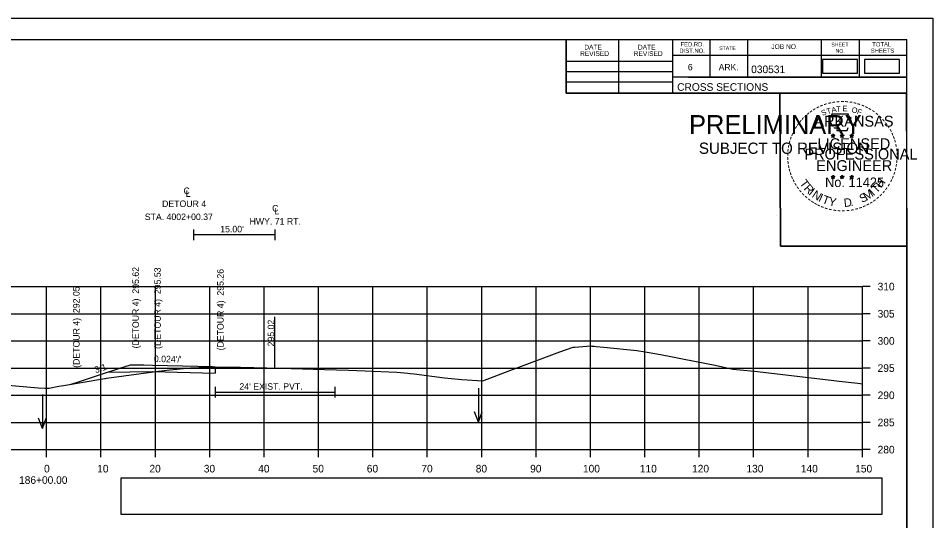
# Model space of a CAD drawing. Extents: x 285 to 4233, y -659 to 3710.
# Drawn here: x 1218.5 to 1386.6, y 2639.9 to 2732.3 of the extents above; entities that cross this region are included whole.
import ezdxf

# ---------------------------------------------------------------- set-up
doc = ezdxf.new("R2010")
doc.units = 0
for name, color, linetype in [('R_Alt Surface', 7, 'Continuous'), ('R_Axis', 7, 'Continuous'), ('R_Axis Annot', 7, 'Continuous'), ('R_Border', 7, 'Continuous'), ('R_Border PE', 7, 'Continuous'), ('R_Border Prem', 7, 'Continuous'), ('R_Detour', 7, 'Continuous'), ('R_Detour Annot', 7, 'Continuous'), ('R_Exist Surface', 7, 'Continuous'), ('R_Grid', 7, 'Continuous'), ('R_No Plot', 7, 'Continuous'), ('R_Water', 7, 'Continuous'), ('R_Water Annot', 7, 'Continuous'), ('R_Xsect Elev', 7, 'Continuous')]:
    doc.layers.add(name, color=color, linetype=linetype)

msp = doc.modelspace()

# ---------------------------------------------------------------- linework, layer by layer
at = {"layer": 'R_Alt Surface'}
for points in [[(1250.68, 2693.45), (1250.68, 2691.45)], [(1265.68, 2693.45), (1265.68, 2691.45)], [(1265.68, 2692.45), (1250.68, 2692.45)], [(1254.68, 2664.51), (1254.68, 2662.51)], [(1254.68, 2663.51), (1276.68, 2663.51)], [(1276.68, 2664.51), (1276.68, 2662.51)]]:
    msp.add_lwpolyline(points, dxfattribs=at)
at = {"layer": 'R_Axis'}
for p, q in [((1373.68, 2652.93), (1373.68, 2682.93)), ((1375.08, 2682.93), (1373.68, 2682.93)), ((1375.08, 2677.93), (1373.68, 2677.93)), ((1375.08, 2672.93), (1373.68, 2672.93)), ((1375.08, 2667.93), (1373.68, 2667.93)), ((1375.08, 2662.93), (1373.68, 2662.93)), ((1375.08, 2657.93), (1373.68, 2657.93)), ((1073.68, 2652.93), (1373.68, 2652.93)), ((1223.68, 2651.53), (1223.68, 2652.93)), ((1233.68, 2651.53), (1233.68, 2652.93)), ((1243.68, 2651.53), (1243.68, 2652.93)), ((1253.68, 2651.53), (1253.68, 2652.93)), ((1263.68, 2651.53), (1263.68, 2652.93)), ((1273.68, 2651.53), (1273.68, 2652.93)), ((1283.68, 2651.53), (1283.68, 2652.93)), ((1293.68, 2651.53), (1293.68, 2652.93)), ((1303.68, 2651.53), (1303.68, 2652.93)), ((1313.68, 2651.53), (1313.68, 2652.93)), ((1323.68, 2651.53), (1323.68, 2652.93)), ((1333.68, 2651.53), (1333.68, 2652.93)), ((1343.68, 2651.53), (1343.68, 2652.93)), ((1353.68, 2651.53), (1353.68, 2652.93)), ((1363.68, 2651.53), (1363.68, 2652.93)), ((1373.68, 2651.53), (1373.68, 2652.93)), ((1375.08, 2652.93), (1373.68, 2652.93))]:
    msp.add_line(p, q, dxfattribs=at)
at = {"layer": 'R_Axis Annot'}
for points in [[(1366.36, 2722.17), (1372.81, 2722.17), (1372.81, 2724.73), (1366.36, 2724.73)], [(1374.05, 2722.17), (1380.51, 2722.17), (1380.51, 2724.73), (1374.05, 2724.73)], [(1237.31, 2641.05), (1377.31, 2641.05), (1377.31, 2647.7), (1237.31, 2647.7)]]:
    msp.add_lwpolyline(points, close=True, dxfattribs=at)
at = {"layer": 'R_Border'}
for p, q in [((1065.68, 2728.39), (1381.86, 2728.39)), ((1319.22, 2718.51), (1319.22, 2728.39)), ((1328.9, 2718.51), (1328.9, 2728.39)), ((1338.76, 2728.39), (1338.76, 2718.51)), ((1345.6, 2728.39), (1345.6, 2721.45)), ((1352.54, 2728.39), (1352.54, 2721.45)), ((1366.12, 2728.39), (1366.12, 2721.45)), ((1373.06, 2728.39), (1373.06, 2721.45)), ((1381.86, 2522.93), (1381.86, 2728.39)), ((1381.86, 2725.45), (1338.76, 2725.45)), ((1381.86, 2725.47), (1381.86, 2725.47)), ((1319.22, 2724.37), (1338.76, 2724.37)), ((1319.22, 2722.51), (1338.76, 2722.51)), ((1319.22, 2720.57), (1338.76, 2720.57)), ((1381.86, 2721.45), (1338.76, 2721.45)), ((1341.72, 2721.45), (1381.86, 2721.45)), ((1381.86, 2718.51), (1319.22, 2718.51))]:
    msp.add_line(p, q, dxfattribs=at)
at = {"layer": 'R_Border PE'}
for p, q in [((1367.94, 2710.76), (1368.29, 2710.65)), ((1367.94, 2710.76), (1368.19, 2710.72)), ((1367.94, 2710.76), (1368.18, 2710.64)), ((1368.07, 2710.36), (1368.29, 2710.65)), ((1368.07, 2710.36), (1368.2, 2710.6)), ((1368.07, 2710.36), (1368.29, 2710.57)), ((1368.29, 2711.02), (1368.25, 2710.77)), ((1368.29, 2710.65), (1368.29, 2711.02)), ((1368.29, 2711.02), (1368.34, 2710.77)), ((1368.64, 2710.76), (1368.29, 2710.65)), ((1368.5, 2710.36), (1368.29, 2710.65)), ((1368.5, 2710.36), (1368.29, 2710.57)), ((1368.64, 2710.76), (1368.35, 2710.72)), ((1368.5, 2710.36), (1368.37, 2710.65)), ((1368.64, 2710.76), (1368.43, 2710.66)), ((1369.61, 2710.76), (1369.96, 2710.65)), ((1369.61, 2710.76), (1369.86, 2710.72)), ((1369.61, 2710.76), (1369.85, 2710.64)), ((1369.74, 2710.36), (1369.96, 2710.65)), ((1369.74, 2710.36), (1369.87, 2710.6)), ((1369.74, 2710.36), (1369.96, 2710.57)), ((1369.96, 2711.02), (1369.92, 2710.77)), ((1369.96, 2710.65), (1369.96, 2711.02)), ((1369.96, 2711.02), (1370.01, 2710.77)), ((1370.31, 2710.76), (1369.96, 2710.65)), ((1370.17, 2710.36), (1369.96, 2710.65)), ((1370.17, 2710.36), (1369.96, 2710.57)), ((1370.31, 2710.76), (1370.02, 2710.72)), ((1370.17, 2710.36), (1370.04, 2710.65)), ((1370.31, 2710.76), (1370.1, 2710.66)), ((1371.38, 2710.75), (1371.72, 2710.64)), ((1371.38, 2710.75), (1371.63, 2710.71)), ((1371.38, 2710.75), (1371.61, 2710.63)), ((1371.51, 2710.34), (1371.72, 2710.64)), ((1371.51, 2710.34), (1371.63, 2710.59)), ((1371.51, 2710.34), (1371.72, 2710.56)), ((1371.72, 2711.01), (1371.68, 2710.75)), ((1371.72, 2710.64), (1371.72, 2711.01)), ((1371.72, 2711.01), (1371.77, 2710.76)), ((1372.07, 2710.75), (1371.72, 2710.64)), ((1371.94, 2710.34), (1371.72, 2710.64)), ((1371.94, 2710.34), (1371.72, 2710.56)), ((1372.07, 2710.75), (1371.79, 2710.7)), ((1371.94, 2710.34), (1371.8, 2710.64)), ((1372.07, 2710.75), (1371.87, 2710.65)), ((1367.94, 2703.19), (1368.29, 2703.08)), ((1367.94, 2703.19), (1368.19, 2703.15)), ((1367.94, 2703.19), (1368.17, 2703.07)), ((1368.07, 2702.78), (1368.29, 2703.08)), ((1368.07, 2702.78), (1368.2, 2703.03)), ((1368.07, 2702.78), (1368.28, 2703)), ((1368.29, 2703.45), (1368.25, 2703.19)), ((1368.5, 2702.78), (1368.28, 2703)), ((1368.29, 2703.08), (1368.29, 2703.45)), ((1368.29, 2703.45), (1368.34, 2703.2)), ((1368.63, 2703.19), (1368.29, 2703.08)), ((1368.5, 2702.78), (1368.29, 2703.08)), ((1368.63, 2703.19), (1368.35, 2703.14)), ((1368.5, 2702.78), (1368.36, 2703.07)), ((1368.63, 2703.19), (1368.43, 2703.09)), ((1369.61, 2703.19), (1369.96, 2703.08)), ((1369.61, 2703.19), (1369.86, 2703.15)), ((1369.61, 2703.19), (1369.84, 2703.07)), ((1369.74, 2702.78), (1369.96, 2703.08)), ((1369.74, 2702.78), (1369.87, 2703.03)), ((1369.74, 2702.78), (1369.95, 2703)), ((1369.96, 2703.45), (1369.91, 2703.19)), ((1370.17, 2702.78), (1369.95, 2703)), ((1369.96, 2703.08), (1369.96, 2703.45)), ((1369.96, 2703.45), (1370, 2703.2)), ((1370.3, 2703.19), (1369.96, 2703.08)), ((1370.17, 2702.78), (1369.96, 2703.08)), ((1370.3, 2703.19), (1370.02, 2703.14)), ((1370.17, 2702.78), (1370.03, 2703.07)), ((1370.3, 2703.19), (1370.1, 2703.09)), ((1371.37, 2703.18), (1371.72, 2703.07)), ((1371.37, 2703.18), (1371.63, 2703.14)), ((1371.37, 2703.18), (1371.61, 2703.06)), ((1371.51, 2702.77), (1371.72, 2703.07)), ((1371.51, 2702.77), (1371.63, 2703.02)), ((1371.51, 2702.77), (1371.72, 2702.99)), ((1371.72, 2703.44), (1371.68, 2703.18)), ((1371.72, 2703.07), (1371.72, 2703.44)), ((1371.72, 2703.44), (1371.77, 2703.19)), ((1372.07, 2703.18), (1371.72, 2703.07)), ((1371.94, 2702.77), (1371.72, 2703.07)), ((1371.94, 2702.77), (1371.72, 2702.99)), ((1372.07, 2703.18), (1371.78, 2703.13)), ((1371.94, 2702.77), (1371.8, 2703.06)), ((1372.07, 2703.18), (1371.87, 2703.08))]:
    msp.add_line(p, q, dxfattribs=at)
for points in [[(1367.98, 2714.64), (1368.25, 2713.82)], [(1371.49, 2713.72), (1371.64, 2714), (1370.95, 2713.98), (1371.1, 2714.64), (1367.98, 2714.64)], [(1368.47, 2712.22), (1368.47, 2712.13), (1369.04, 2712.11), (1368.98, 2711.64), (1370.85, 2711.64), (1371.05, 2712.18)], [(1368.29, 2711.02), (1368.5, 2710.36), (1367.94, 2710.76), (1368.64, 2710.76), (1368.07, 2710.36), (1368.29, 2711.02)], [(1369.96, 2711.02), (1370.17, 2710.36), (1369.61, 2710.76), (1370.31, 2710.76), (1369.74, 2710.36), (1369.96, 2711.02)], [(1371.72, 2711.01), (1371.94, 2710.34), (1371.38, 2710.75), (1372.07, 2710.75), (1371.51, 2710.34), (1371.72, 2711.01)], [(1368.29, 2703.45), (1368.5, 2702.78), (1367.94, 2703.19), (1368.63, 2703.19), (1368.07, 2702.78), (1368.29, 2703.45)], [(1369.96, 2703.45), (1370.17, 2702.78), (1369.61, 2703.19), (1370.3, 2703.19), (1369.74, 2702.78), (1369.96, 2703.45)], [(1371.72, 2703.44), (1371.94, 2702.77), (1371.37, 2703.18), (1372.07, 2703.18), (1371.51, 2702.77), (1371.72, 2703.44)]]:
    msp.add_lwpolyline(points, dxfattribs=at)
for centre, radius in [((1368.29, 2710.65), 0.172), ((1368.29, 2710.65), 0.145), ((1368.29, 2710.65), 0.116), ((1368.29, 2710.65), 0.0991), ((1368.29, 2710.65), 0.0747), ((1368.29, 2710.65), 0.0495), ((1368.29, 2710.65), 0.0296), ((1369.96, 2710.65), 0.172), ((1369.96, 2710.65), 0.145), ((1369.96, 2710.65), 0.116), ((1369.96, 2710.65), 0.0991), ((1369.96, 2710.65), 0.0747), ((1369.96, 2710.65), 0.0495), ((1369.96, 2710.65), 0.0296), ((1371.72, 2710.64), 0.172), ((1371.72, 2710.64), 0.145), ((1371.72, 2710.64), 0.116), ((1371.72, 2710.64), 0.0991), ((1371.72, 2710.64), 0.0747), ((1371.72, 2710.64), 0.0495), ((1371.72, 2710.64), 0.0296), ((1368.29, 2703.08), 0.172), ((1368.29, 2703.08), 0.145), ((1368.29, 2703.08), 0.116), ((1368.29, 2703.08), 0.0991), ((1368.29, 2703.08), 0.0747), ((1368.29, 2703.08), 0.0495), ((1368.29, 2703.08), 0.0296), ((1369.95, 2703.08), 0.172), ((1369.95, 2703.08), 0.145), ((1369.95, 2703.08), 0.116), ((1369.95, 2703.08), 0.0991), ((1369.95, 2703.08), 0.0747), ((1369.95, 2703.08), 0.0495), ((1369.95, 2703.08), 0.0296), ((1371.72, 2703.07), 0.172), ((1371.72, 2703.07), 0.145), ((1371.72, 2703.07), 0.116), ((1371.72, 2703.07), 0.0991), ((1371.72, 2703.07), 0.0747), ((1371.72, 2703.07), 0.0495), ((1371.72, 2703.07), 0.0296)]:
    msp.add_circle(centre, radius, dxfattribs=at)
at = {"layer": 'R_Detour'}
msp.add_line((1254.69, 2668.19), (1254.69, 2667.02), dxfattribs=at)
for points in [[(1228.2, 2664.98), (1229.76, 2665.49), (1233.4, 2666.68), (1237.17, 2667.92), (1239.11, 2668.55), (1241.55, 2668.5), (1243.13, 2668.46), (1254.19, 2668.2), (1254.69, 2668.19)], [(1234.85, 2667.16), (1243.13, 2667.29), (1254.69, 2667.02), (1254.69, 2667.02)]]:
    msp.add_lwpolyline(points, dxfattribs=at)
at = {"layer": 'R_Exist Surface'}
msp.add_lwpolyline([(1213.73, 2665.03), (1222.13, 2664.31), (1223.42, 2664.26), (1224.14, 2664.23), (1225.92, 2664.58), (1226.8, 2664.74), (1234.37, 2666.02), (1234.52, 2666.04), (1234.68, 2666.07), (1244.26, 2667.36), (1246.36, 2667.62), (1250.16, 2667.99), (1251.75, 2668.06), (1254.69, 2668.19), (1259.31, 2668.09), (1266.66, 2667.93), (1274.8, 2667.69), (1279.18, 2667.56), (1282.24, 2667.43), (1288.11, 2667.19), (1290.09, 2666.99), (1290.54, 2666.95), (1291.26, 2666.86), (1296.85, 2666.12), (1300.01, 2665.86), (1303.87, 2665.56), (1308.86, 2667.49), (1310.02, 2667.94), (1318.08, 2670.93), (1320.49, 2671.78), (1320.78, 2671.8), (1323.76, 2672), (1323.91, 2671.99), (1324.09, 2671.98), (1324.25, 2671.97), (1324.38, 2671.96), (1324.75, 2671.92), (1326.17, 2671.77), (1332.2, 2671.17), (1333.75, 2670.94), (1335.89, 2670.53), (1338.16, 2670.12), (1340.58, 2669.63), (1345.03, 2668.76), (1346.6, 2668.44), (1349.85, 2667.72), (1351.23, 2667.62), (1353.84, 2667.39), (1367.91, 2665.69), (1369.4, 2665.51), (1372.83, 2665.13), (1373.68, 2665.01)], dxfattribs=at)
at = {"layer": 'R_Grid'}
for p, q in [((1073.68, 2682.93), (1373.68, 2682.93)), ((1223.68, 2652.93), (1223.68, 2682.93)), ((1233.68, 2652.93), (1233.68, 2682.93)), ((1243.68, 2652.93), (1243.68, 2682.93)), ((1253.68, 2652.93), (1253.68, 2682.93)), ((1263.68, 2652.93), (1263.68, 2682.93)), ((1273.68, 2652.93), (1273.68, 2682.93)), ((1283.68, 2652.93), (1283.68, 2682.93)), ((1293.68, 2652.93), (1293.68, 2682.93)), ((1303.68, 2652.93), (1303.68, 2682.93)), ((1313.68, 2652.93), (1313.68, 2682.93)), ((1323.68, 2652.93), (1323.68, 2682.93)), ((1333.68, 2652.93), (1333.68, 2682.93)), ((1343.68, 2652.93), (1343.68, 2682.93)), ((1353.68, 2652.93), (1353.68, 2682.93)), ((1363.68, 2652.93), (1363.68, 2682.93)), ((1373.68, 2652.93), (1373.68, 2682.93)), ((1073.68, 2677.93), (1373.68, 2677.93)), ((1073.68, 2672.93), (1373.68, 2672.93)), ((1073.68, 2667.93), (1373.68, 2667.93)), ((1073.68, 2662.93), (1373.68, 2662.93)), ((1073.68, 2657.93), (1373.68, 2657.93)), ((1073.68, 2652.93), (1373.68, 2652.93))]:
    msp.add_line(p, q, dxfattribs=at)
at = {"layer": 'R_No Plot'}
for p, q in [((1053.28, 2732.28), (1386.61, 2732.28)), ((1357.89, 2696.05), (1357.89, 2696.05))]:
    msp.add_line(p, q, dxfattribs=at)
for points in [[(1053.27, 2732.28), (1386.61, 2732.28), (1386.61, 2518.95), (1053.27, 2518.95)], [(1299.6, 2728.39), (1319.22, 2728.39), (1319.22, 2718.51), (1335.33, 2718.51), (1358.53, 2718.51), (1358.65, 2690.35), (1381.86, 2690.35), (1381.86, 2522.93), (1065.68, 2522.93), (1065.68, 2728.39)], [(1358.53, 2718.51), (1381.74, 2718.51), (1381.86, 2690.35), (1358.65, 2690.35)]]:
    msp.add_lwpolyline(points, close=True, dxfattribs=at)
at = {"layer": 'R_Water Annot'}
for p, q in [((1303.07, 2664.25), (1303.07, 2657.97)), ((1222.91, 2663.07), (1222.91, 2656.79)), ((1303.07, 2657.97), (1302.37, 2659.89)), ((1303.07, 2657.97), (1303.77, 2659.89)), ((1222.91, 2656.79), (1222.21, 2658.71)), ((1222.91, 2656.79), (1223.61, 2658.71))]:
    msp.add_line(p, q, dxfattribs=at)
at = {"layer": 'R_Xsect Elev'}
msp.add_line((1265.68, 2667.95), (1265.68, 2677.37), dxfattribs=at)

# ---------------------------------------------------------------- texts
at = {"layer": 'R_Alt Surface'}
for s, height, p in [('C', 1.2, (1248.86, 2699.95)), ('L', 1.2, (1249.25, 2699.43)), ('DETOUR 4', 1.199, (1244.92, 2697.56)), ('C', 1.2, (1265.16, 2696.73)), ('L', 1.2, (1265.55, 2696.2)), ('STA. 4002+00.37', 1.1985, (1241.74, 2695.16)), ('HWY. 71 RT.', 1.1985, (1261.01, 2694.33))]:
    msp.add_text(s, height=height, dxfattribs=at).set_placement(p)
at = {"layer": 'R_Axis Annot'}
for s, p in [('310', (1376.48, 2682.23)), ('305', (1376.48, 2677.23)), ('300', (1376.48, 2672.23)), ('295', (1376.48, 2667.23)), ('290', (1376.48, 2662.23)), ('285', (1376.48, 2657.23)), ('280', (1376.48, 2652.23)), ('0', (1223.22, 2648.73)), ('10', (1232.99, 2648.73)), ('20', (1242.59, 2648.73)), ('30', (1252.59, 2648.73)), ('40', (1262.59, 2648.73)), ('50', (1272.59, 2648.73)), ('60', (1282.56, 2648.73)), ('70', (1292.59, 2648.73)), ('80', (1302.59, 2648.73)), ('90', (1312.59, 2648.73)), ('100', (1322.3, 2648.73)), ('110', (1332.76, 2648.73)), ('120', (1342.36, 2648.73)), ('130', (1352.36, 2648.73)), ('140', (1362.36, 2648.73)), ('150', (1372.36, 2648.73)), ('186+00.00', (1218.62, 2646.63))]:
    msp.add_text(s, height=1.4, dxfattribs=at).set_placement(p)
at = {"layer": 'R_Border'}
for s, height, p in [('DATE', 0.879, (1322.55, 2726.53)), ('DATE', 0.879, (1332.41, 2726.53)), ('FED.RD.', 0.782, (1340.24, 2727.11)), ('STATE', 0.684, (1347.36, 2726.43)), ('JOB NO.', 0.879, (1356.94, 2726.63)), ('SHEET', 0.684, (1367.98, 2727.11)), ('TOTAL', 0.782, (1375.5, 2727.11)), ('REVISED', 0.879, (1321.77, 2725.35)), ('REVISED', 0.879, (1331.63, 2725.35)), ('DIST.NO.', 0.782, (1340.04, 2725.93)), ('NO.', 0.684, (1368.76, 2725.93)), ('SHEETS', 0.782, (1375.22, 2725.93)), ('6', 1.17, (1341.6, 2722.71)), ('ARK.', 1.172, (1347.26, 2722.71)), ('030531', 1.4, (1353.23, 2722.19)), ('CROSS SECTIONS', 1.4, (1339.62, 2718.94))]:
    msp.add_text(s, height=height, rotation=360, dxfattribs=at).set_placement(p)
at = {"layer": 'R_Border PE'}
for s, height, rotation, p in [('-', 1.6, 10.2193, (1368.16, 2716.17)), ('-', 1.6, 5.8968, (1368.89, 2716.28)), ('-', 1.6, 0.1862, (1369.66, 2716.35)), ('-', 1.6, 357.743, (1370.38, 2716.34)), ('-', 1.6, 352.1617, (1371.13, 2716.29)), ('-', 1.6, 36.2317, (1364.29, 2714.42)), ('-', 1.6, 34.0636, (1364.87, 2714.81)), ('-', 1.6, 28.7918, (1365.46, 2715.18)), ('-', 1.6, 24.3072, (1366.1, 2715.5)), ('S', 1, 21.594, (1366.34, 2714.32)), ('-', 1.6, 19.1761, (1366.73, 2715.77)), ('T', 1, 16.4036, (1367.25, 2714.65)), ('-', 1.6, 13.6301, (1367.48, 2716.01)), ('A', 1, 11.2132, (1368.08, 2714.9)), ('T', 1, 6.0228, (1368.93, 2715.07)), ('E', 1, 0.8323, (1370.03, 2715.18)), ('O', 1, 350.4515, (1371.64, 2714.97)), ('-', 1.6, 347.2049, (1371.85, 2716.17)), ('F', 1, 340.0707, (1372.59, 2714.74)), ('-', 1.6, 342.3362, (1372.48, 2716.02)), ('-', 1.6, 337.8551, (1373.22, 2715.79)), ('-', 1.6, 334.1211, (1373.85, 2715.52)), ('-', 1.6, 329.6409, (1374.43, 2715.24)), ('-', 1.6, 325.8627, (1375.07, 2714.88)), ('-', 1.6, 48.423, (1362.93, 2713.15)), ('-', 1.6, 42.9622, (1363.38, 2713.62)), ('-', 1.6, 38.9507, (1363.81, 2714.04)), ('ARKANSAS', 2, 360, (1364.84, 2712.35)), ('-', 1.6, 320.5297, (1375.68, 2714.45)), ('-', 1.6, 315.5786, (1376.28, 2713.96)), ('-', 1.6, 309.8797, (1376.85, 2713.41)), ('-', 1.6, 58.0706, (1361.79, 2711.57)), ('-', 1.6, 54.2325, (1362.12, 2712.09)), ('-', 1.6, 50.6142, (1362.53, 2712.66)), ('-', 1.6, 306.6522, (1377.37, 2712.81)), ('-', 1.4, 303.6753, (1377.86, 2712.24)), ('-', 1.6, 72.3945, (1361, 2709.71)), ('-', 1.6, 67.7743, (1361.22, 2710.34)), ('-', 1.6, 62.8713, (1361.48, 2710.95)), ('LICENSED', 2, 360, (1365.43, 2708.21)), ('DWB', 0.01, 360, (1368.28, 2710.65)), ('DWB', 0.01, 360, (1369.95, 2710.65)), ('DWB', 0.01, 360, (1371.71, 2710.64)), ('-', 1.6, 299.6684, (1378.18, 2711.64)), ('-', 1.6, 294.6628, (1378.5, 2711.03)), ('-', 1.6, 290.5728, (1378.76, 2710.45)), ('-', 1.6, 81.2013, (1360.67, 2708.28)), ('-', 1.6, 75.461, (1360.8, 2709)), ('-', 1.6, 285.1233, (1378.99, 2709.87)), ('-', 1.6, 280.5493, (1379.19, 2709.13)), ('-', 1.6, 89.0622, (1360.57, 2706.89)), ('-', 1.6, 85.1863, (1360.59, 2707.59)), ('PROFESSIONAL', 2, 360, (1363.01, 2706.3)), ('-', 1.6, 276.5962, (1379.35, 2708.36)), ('-', 1.6, 274.3301, (1379.41, 2707.64)), ('-', 1.6, 269.9407, (1379.45, 2707)), ('-', 1.6, 94.1959, (1360.6, 2706.17)), ('-', 1.6, 98.9479, (1360.68, 2705.5)), ('-', 1.6, 101.7149, (1360.81, 2704.77)), ('ENGINEER', 2, 360, (1365.2, 2704.18)), ('-', 1.6, 260.9953, (1379.36, 2705.68)), ('-', 1.6, 263.5172, (1379.43, 2706.34)), ('-', 1.6, 105.4578, (1360.97, 2704.17)), ('-', 1.6, 109.0874, (1361.19, 2703.54)), ('-', 1.6, 252.8681, (1379.07, 2704.29)), ('-', 1.6, 255.7626, (1379.25, 2705.01)), ('-', 1.6, 114.0643, (1361.44, 2702.94)), ('-', 1.6, 115.7289, (1361.75, 2702.33)), ('-', 1.6, 120.4471, (1362.1, 2701.74)), ('T', 1.54, 306.0406, (1362.05, 2701.92)), ('No. 11425', 1.757, 360, (1366.82, 2701.23)), ('DWB', 0.01, 360, (1368.27, 2703.08)), ('DWB', 0.01, 360, (1369.94, 2703.08)), ('DWB', 0.01, 360, (1371.71, 2703.07)), ('T', 1.54, 46.6444, (1376.28, 2700.01)), ('H', 1.54, 54.6088, (1377.17, 2700.95)), ('-', 1.6, 239.0712, (1378.19, 2702.23)), ('-', 1.6, 244.6197, (1378.58, 2702.98)), ('-', 1.6, 247.8887, (1378.84, 2703.61)), ('-', 1.6, 125.8934, (1362.51, 2701.18)), ('-', 1.6, 130.7181, (1362.97, 2700.63)), ('-', 1.6, 134.2238, (1363.49, 2700.08)), ('R', 1.54, 314.005, (1362.81, 2700.87)), ('I', 1.54, 321.9694, (1363.71, 2699.94)), ('N', 1.54, 326.5002, (1364.28, 2699.47)), ('M', 1.54, 32.6563, (1374.43, 2698.69)), ('I', 1.54, 42.1136, (1375.72, 2699.53)), ('-', 1.6, 231.2538, (1377.36, 2701.01)), ('-', 1.6, 233.8452, (1377.79, 2701.58)), ('-', 1.6, 138.9338, (1364.01, 2699.62)), ('-', 1.6, 144.6463, (1364.57, 2699.21)), ('-', 1.6, 148.0898, (1365.13, 2698.84)), ('I', 1.54, 335.3603, (1365.48, 2698.68)), ('T', 1.54, 339.8912, (1366.15, 2698.35)), ('Y', 1.54, 347.8556, (1367.36, 2697.91)), ('D', 1.54, 6.3969, (1370.35, 2697.55)), ('S', 1.54, 26.9312, (1373.59, 2698.28)), ('-', 1.6, 212.2491, (1375.27, 2699.08)), ('-', 1.6, 215.7363, (1375.81, 2699.47)), ('-', 1.6, 221.0851, (1376.35, 2699.94)), ('-', 1.6, 225.7653, (1376.88, 2700.45)), ('-', 1.6, 151.5704, (1365.71, 2698.52)), ('-', 1.6, 154.6002, (1366.23, 2698.27)), ('-', 1.6, 158.5612, (1366.85, 2698.02)), ('-', 1.6, 162.7983, (1367.54, 2697.8)), ('-', 1.6, 167.5555, (1368.26, 2697.64)), ('-', 1.6, 173.1155, (1369.03, 2697.53)), ('-', 1.6, 176.5183, (1369.78, 2697.48)), ('-', 1.6, 181.5918, (1370.52, 2697.49)), ('-', 1.6, 185.8167, (1371.33, 2697.57)), ('-', 1.6, 191.2858, (1372.06, 2697.7)), ('.', 1.54, 13.7642, (1371.54, 2697.68)), ('-', 1.6, 195.4743, (1372.79, 2697.9)), ('-', 1.6, 200.7184, (1373.47, 2698.14)), ('-', 1.6, 204.2516, (1374.09, 2698.42)), ('-', 1.6, 207.3568, (1374.71, 2698.74))]:
    msp.add_text(s, height=height, rotation=rotation, dxfattribs=at).set_placement(p)
at = {"layer": 'R_Border Prem'}
for s, height, p in [('PRELIMINARY', 3.5, (1341.81, 2710.97)), ('DWB', 0.01, (1342.55, 2712.82)), ('SUBJECT TO REVISION', 2.0751, (1343.62, 2707.34))]:
    msp.add_text(s, height=height, rotation=360, dxfattribs=at).set_placement(p)
at = {"layer": 'R_Detour Annot'}
for s, rotation, p in [('(DETOUR 4)  295.62', 90, (1240.66, 2671.55)), ('(DETOUR 4)  295.53', 90, (1244.68, 2671.46)), ('(DETOUR 4)  295.26', 90, (1256.24, 2671.19)), ('(DETOUR 4)  292.05', 90, (1229.75, 2667.98)), ("0.024'/'", 358.648, (1243.4, 2669.05)), ('3:1', 18.1439, (1232.71, 2666.98))]:
    msp.add_text(s, height=1.2, rotation=rotation, dxfattribs=at).set_placement(p)
at = {"layer": 'R_Water'}
for s, p in [("15.00'", (1255.61, 2692.9)), ("24' EXIST. PVT.", (1259.13, 2663.95))]:
    msp.add_text(s, height=1.2, dxfattribs=at).set_placement(p)
at = {"layer": 'R_Xsect Elev'}
msp.add_text('295.02', height=1.2, rotation=90, dxfattribs=at).set_placement((1265.54, 2671.92))

doc.saveas('drawing.dxf')
